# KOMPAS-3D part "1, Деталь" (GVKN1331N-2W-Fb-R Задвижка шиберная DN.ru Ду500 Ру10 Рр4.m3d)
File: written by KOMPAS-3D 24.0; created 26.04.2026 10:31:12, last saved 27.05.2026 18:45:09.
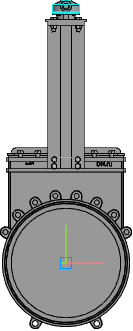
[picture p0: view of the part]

Document properties: Автор: R2D2; Полное имя файла: E:\Работа\Зайцев\АУТСОРС\Даня\GVKN1331N-2W-Fb-R Задвижка шиберная DN.ru Ду400-600 Ру4-6\исходные материалы\DN500\GVKN1331N-2W-Fb-R Задвижка шиберная DN.ru Ду500 Ру10 Рр4.m3d

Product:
- Component [standard]: Hexagon head screw ISO 4017 - М10 x 25  | qty 4  | Масса: 0.026096; Рассекать на разрезах: no; source file: C:\Program Files\ASCON\KOMPAS-3D v24\Libs\PolynomLib\DATA\vault\methods\kompas\3d\PLib_Bolt_1_ISO_1100.m3d
- Body: Тело 4  | qty 1
    Масса: 180.082087
- Body: Тело 5  | qty 1
    Масса: 180.082087
- Body: Тело 6  | qty 1
    Масса: 14.189836
- Body: Тело 7  | qty 1
    Масса: 180.082087
- Body: Тело 8  | qty 1
    Масса: 5.600139
- Body: Тело 12  | qty 1
    Масса: 5.600139
- Component [standard]: (unnamed)  | qty 4  | Масса: 0.1215; Рассекать на разрезах: no; additional columns: М16-6gx55; Болт; ГОСТ 7805-70
- Component [standard]: Гайка М16-6H ГОСТ 5915-70  | qty 4  | Масса: 0.03761; Рассекать на разрезах: no; source file: C:\Program Files\ASCON\KOMPAS-3D v24\Libs\PolynomLib\DATA\vault\methods\kompas\3d\PLib_Nut_OST92_900.m3d
- Component [standard]: Болт М18-6gx30 ГОСТ 7805-70  | qty 1  | Масса: 0.1143; Рассекать на разрезах: no; source file: C:\Program Files\ASCON\KOMPAS-3D v24\Libs\PolynomLib\DATA\vault\methods\kompas\3d\PLib_Bolt_1_900.m3d
- Component [standard]: Болт М18-6gx30 ГОСТ 7805-70  | qty 7  | Масса: 0.1143; Рассекать на разрезах: no
- Component [standard]: Болт М16-6gx30 ГОСТ 7805-70  | qty 1  | Масса: 0.08324; Рассекать на разрезах: no; source file: C:\Program Files\ASCON\KOMPAS-3D v24\Libs\PolynomLib\DATA\vault\methods\kompas\3d\PLib_Bolt_1_900.m3d
- Component [standard]: Болт М16-6gx30 ГОСТ 7805-70  | qty 7  | Масса: 0.08324; Рассекать на разрезах: no
- Body: Тело 14  | qty 1
    Масса: 180.082087
- Part/product: 1  | designation Деталь
    Масса: 18.2
    Раздел спецификации: Прочие изделия
    Примечание: D050-23732

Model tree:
1. Смещенная плоскость:2
2. Корпус
3. Элемент вращения:1
     Угол 1 = 360
4. Ушко  (with: Ребро.Элемент вращения:1)
5. Элемент выдавливания:5
6. Диск  (with: Ребро.Элемент вращения:1)
7. Элемент выдавливания:3
     Расстояние 1 = 10
8. Скругление:10  (with: Ребро.Элемент выдавливания:5)
     Радиус = 5
9. Скругление:11  (with: Ребро.Элемент выдавливания:5)
     Радиус = 2
10. Массив по концентрической сетке:7  (with: Элемент выдавливания:5, Скругление:10, Скругление:11, Грань.Элемент вращения:1)  (10 pattern instances)
11. Корпус штока
12. Элемент выдавливания:6  (with: Грань.Элемент вращения:1)
13. Эскиз:3  (with: Грань.Элемент выдавливания:5, Ребро.Скругление:11)
14. Элемент выдавливания:12
15. Массив по концентрической сетке:9  (with: Элемент выдавливания:12, Эскиз:3, Грань.Элемент вращения:1)  (17 pattern instances)
     Шаг 2 = 360
16. Зеркальный массив:2
17. Экземпляр ( 1 )
18. Экземпляр ( 2 )  (with: Массив по концентрической сетке:9, Экземпляр ( 1 ), Элемент выдавливания:12)
19. Экземпляр ( 3 )  (with: Элемент выдавливания:12)
20. Экземпляр ( 4 )  (with: Элемент выдавливания:12)
21. Экземпляр ( 5 )  (with: Элемент выдавливания:12)
22. Экземпляр ( 6 )  (with: Элемент выдавливания:12)
23. Экземпляр ( 7 )  (with: Элемент выдавливания:12)
24. Экземпляр ( 8 )  (with: Элемент выдавливания:12)
25. Экземпляр ( 9 )  (with: Элемент выдавливания:12)
26. Экземпляр ( 10 )  (with: Элемент выдавливания:12)
27. Экземпляр ( 12 )  (with: Элемент выдавливания:12)
28. Экземпляр ( 13 )  (with: Элемент выдавливания:12)
29. Экземпляр ( 14 )  (with: Элемент выдавливания:12)
30. Экземпляр ( 15 )  (with: Элемент выдавливания:12)
31. Экземпляр ( 18 )  (with: Элемент выдавливания:12)
32. Экземпляр ( 19 )  (with: Элемент выдавливания:12)
33. Экземпляр ( 20 )  (with: Элемент выдавливания:12)
34. Эскиз:24  (with: Грань.Элемент вращения:1, Ребро.Элемент вращения:1)
35. Элемент выдавливания:36
     Расстояние 2 = 2
36. Зеркальный массив:4  (with: Экземпляр ( 1 ), Экземпляр ( 2 ), Элемент выдавливания:36)
37. Резиновое уплотнение
38. Элемент выдавливания:4
39. Скругление:2  (with: Грань.Элемент выдавливания:4)
     Радиус = 2
40. Скругление:4  (with: Ребро.Элемент выдавливания:6)
     Радиус = 2
41. фланец  (with: Грань.Элемент выдавливания:6, Ребро.Элемент выдавливания:6)
42. Элемент выдавливания:13
     Расстояние 2 = 15
43. Скругление:12  (with: Ребро.Элемент выдавливания:13)
     Радиус = 10
44. Массив по сетке:1  (with: Элемент выдавливания:13, Эскиз:4, Скругление:12)  (2 pattern instances)
     Шаг 1 = 50; Угол раствора = 90
45. Эскиз:5  (with: Грань.Элемент выдавливания:6, Ребро.Элемент выдавливания:13)  (labels: Ребро.Элемент выдавливания:13.Экземпляр ( 2, 1 ))
46. Элемент выдавливания:14  (with: Грань.Элемент вращения:1)
     Расстояние 1 = 24.75; Смещение 1 = 1
47. Эскиз:6  (with: Грань.Элемент выдавливания:6, Ребро.Элемент выдавливания:13, Ребро.Элемент выдавливания:14)  (labels: Ребро.Элемент выдавливания:13.Экземпляр ( 2, 1 ))
48. Элемент выдавливания:15  (with: Грань.Элемент вращения:1)
     Расстояние 1 = 24.75; Смещение 1 = 1
49. Эскиз:7  (with: Вершина.Элемент выдавливания:14, Ребро.Элемент выдавливания:14)  (labels: Грань.Элемент выдавливания:13.Экземпляр ( 2, 1 ))
50. Элемент выдавливания:16
51. Эскиз:8  (with: Ребро.Элемент выдавливания:15)  (labels: Грань.Элемент выдавливания:13.Экземпляр ( 2, 1 ))
52. Элемент выдавливания:17  (with: Грань.Элемент выдавливания:16)
     Расстояние 1 = 670
53. Смещенная плоскость:3
54. Эскиз:9  (with: Грань.Элемент выдавливания:16, Вершина.Элемент выдавливания:17, Ребро.Элемент выдавливания:16, Ребро.Элемент выдавливания:17)
55. Элемент выдавливания:18
     Расстояние 2 = 15
56. Скругление:13  (with: Ребро.Элемент выдавливания:16, Ребро.Элемент выдавливания:17)
     Радиус = 15
57. Эскиз:10  (with: Грань.Элемент выдавливания:18, Ребро.Скругление:13, Ребро.Элемент выдавливания:18, Ребро.Элемент выдавливания:17)
58. Элемент выдавливания:19
     Расстояние 1 = 10
59. Эскиз:11  (with: Грань.Элемент выдавливания:13, Ребро.Элемент выдавливания:13)
60. Элемент выдавливания:20
     Расстояние 1 = 10
61. Эскиз:12  (with: Грань.Элемент выдавливания:20, Ребро.Элемент выдавливания:13, Ребро.Элемент выдавливания:17, Вершина.Элемент выдавливания:17, Вершина.Элемент выдавливания:18)
62. Элемент выдавливания:21
     Расстояние 1 = 10
63. Фаска:1  (with: Ребро.Элемент выдавливания:21)
     Угол = 60; Длина 1 = 20; Длина 2 = 34.641
64. Фаска:2  (with: Ребро.Элемент выдавливания:21)
     Угол = 60; Длина 1 = 20; Длина 2 = 34.641
65. Эскиз:13  (with: Грань.Элемент выдавливания:13)
66. Элемент выдавливания:22  (with: Грань.Элемент выдавливания:21)
     Расстояние 1 = 45; Смещение 1 = 25
67. Скругление:14  (with: Ребро.Элемент выдавливания:22)
     Радиус = 20
68. Эскиз:14  (with: Грань.Элемент выдавливания:21, Ребро.Элемент выдавливания:22, Ребро.Элемент выдавливания:21)
69. Элемент выдавливания:23
     Расстояние 1 = 30
70. Эскиз:15  (with: Грань.Элемент выдавливания:23, Ребро.Элемент выдавливания:23)
71. Элемент выдавливания:24  (with: Грань.Элемент выдавливания:19)
     Расстояние 1 = 570
72. Эскиз:16  (with: Грань.Элемент выдавливания:19, Ребро.Элемент выдавливания:24)
73. Элемент выдавливания:25  (with: Грань.Элемент выдавливания:18)
     Расстояние 2 = 25
74. Массив по концентрической сетке:10  (with: Элемент выдавливания:25, Эскиз:16, Грань.Элемент выдавливания:24)  (4 pattern instances)
     Шаг 2 = 360
75. Эскиз:17  (with: Грань.Элемент выдавливания:19, Ребро.Элемент выдавливания:24, Ребро.Элемент выдавливания:19)
76. Элемент выдавливания:26
     Расстояние 1 = 25
77. ИСО фланец  (with: Грань.Элемент выдавливания:26, Ребро.Элемент выдавливания:26)
78. Элемент выдавливания:7
     Расстояние 1 = 10
79. отв. исо фланца  (with: Грань.Элемент выдавливания:7, Ребро.Элемент выдавливания:7)
80. Элемент выдавливания:27  (with: Грань.Элемент выдавливания:7)
     Расстояние 2 = 10
81. Массив по концентрической сетке:11  (with: Элемент выдавливания:27, Грань.Элемент выдавливания:7)  (4 pattern instances)
     Шаг 2 = 360
82. Эскиз:18  (with: Грань.Элемент выдавливания:7, Ребро.Элемент выдавливания:7)
83. Элемент выдавливания:28
     Расстояние 1 = 2
84. Смещенная плоскость:4  (with: Грань.Элемент выдавливания:7)
     Расстояние = 0.5
85. Эскиз:19  (with: Ребро.Элемент выдавливания:7)
86. Элемент выдавливания:29
     Расстояние 1 = 30
87. Эскиз:20  (with: Ребро.Элемент выдавливания:29)
88. Элемент выдавливания:30
     Расстояние 2 = 5
89. Элемент по сечениям:1  (with: Грань.Элемент выдавливания:30, Грань.Элемент выдавливания:29)
90. Скругление:15  (with: Ребро.Элемент выдавливания:30)
     Радиус = 5
91. ЛЕЙБЛ  (with: Ребро.Скругление:4)
92. Элемент выдавливания:31  (with: Грань.Элемент выдавливания:6)
     Расстояние 1 = 29.75; Смещение 1 = 1
93. Нормальная плоскость:1  (with: Грань.Элемент выдавливания:29)
94. Эскиз:21
95. Элемент выдавливания:32
     Расстояние 1 = 100
96. Фаска:3  (with: Ребро.Элемент выдавливания:32)
     Угол = 45; Длина 1 = 10; Длина 2 = 10
97. Эскиз:22  (with: Грань.Элемент выдавливания:32, Ребро.Фаска:3)
98. Элемент выдавливания:33
     Расстояние 1 = 20
99. Массив по концентрической сетке:2  (with: Грань.Элемент выдавливания:7)  (4 pattern instances)
     Шаг 2 = 360
100. Массив по концентрической сетке:3  (with: Грань.Элемент выдавливания:26)  (4 pattern instances)
     Шаг 2 = 360
101. Эскиз:23  (with: Грань.Элемент выдавливания:16, Ребро.Элемент выдавливания:16)
102. Элемент выдавливания:34
103. Зеркальный массив:3  (with: Экземпляр ( 1 ), Экземпляр ( 2 ), Элемент выдавливания:34)
104. Эскиз:25  (labels: Грань.Элемент выдавливания:5.Экземпляр ( 1, 13 ); Ребро.Элемент выдавливания:12.Экземпляр ( 1, 13 ))
105. Элемент выдавливания:37
106. Массив по концентрической сетке:12  (with: Элемент выдавливания:37, Эскиз:25, Грань.Элемент выдавливания:7, Грань.Элемент выдавливания:19, Грань.Элемент выдавливания:18, Грань.Элемент выдавливания:21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)  (labels: Ребро.Элемент выдавливания:27.Экземпляр ( 1, 4 ); Грань.Элемент выдавливания:25.Экземпляр ( 1, 2 ); Грань.Элемент выдавливания:34.Экземпляр ( 2 ))  (12 pattern instances)
     Шаг 2 = 360

Expressions: v30-20; v161-20; D2-5; D/2-D1/2; L/2+5; 360/n/2; D1*0.85; id3-id4*2; DS*2; D1/4+10; D2-20; v4384_v161-20; H1-H1/2.5-50; H1/2.5
Referenced files in C:\Program Files\ASCON\KOMPAS-3D v24\Libs\PolynomLib\DATA\vault\Methods\Kompas\3D\: PLib_Bolt_1_ISO_1100.m3d, PLib_Bolt_1_900.m3d, PLib_Nut_OST92_900.m3d
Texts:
  BOSimple***PART:f114febc-ab7b-6638-bb5e-15f0e2e47160***SHORTLOC:A259_7B16EF33AB1642D2[16;1,5;25;10;-;Undefined]
  BOSimple***PART:d5043757-7383-cfe0-2773-bdcfb0c19ea2***SHORTLOC:Root±30±20±10±80±10±©{}30±©{BASE}130±30[Нет;Без покрытия;Без указания материала;55;16;24;2;-]
  BOSimple***PART:17b45fe1-43c8-f41a-5df4-ae57481e6c3b***SHORTLOC:Root±30±10±20±©{}110±10±50±60[Нет;Без покрытия;Без указания материала;-;16;2;24]
  BOSimple***PART:58fea51c-4c27-65e8-868c-b0420730e5b8***SHORTLOC:Root±30±20±10±80±10±©{}30±©{BASE}130±30[Нет;Без покрытия;Без указания материала;30;18;27;2,5;-]
  BOSimple***PART:296a4829-a4b6-4e05-4821-ac6adc08aeaf***SHORTLOC:Root±30±20±10±80±10±©{}30±©{BASE}130±30[Нет;Без покрытия;Без указания материала;30;16;24;2;-]
  GOST 26.020 Pr3
  var3D
  ширина затвора по металлу
  Диаметр исо фланца
  id4
  Диуметр отверстия  исо фланца
  id3
  ось отв. исо фланца
  id5
  ds1
  Hexagon head screw ISO 4017 - М10 x 25 (1)
  hole1
  hole2
  Деталь (1)
  Гайка М16-6H ГОСТ 5915-70 (1)
  bcut1
  hcut1
  cut1
  Болт М18-6gx30 ГОСТ 7805-70 (1)
  Болт М18-6gx30 ГОСТ 7805-70 (2)
  Болт М18-6gx30 ГОСТ 7805-70 (3)
  Болт М18-6gx30 ГОСТ 7805-70 (4)
  Болт М18-6gx30 ГОСТ 7805-70 (5)
  Болт М18-6gx30 ГОСТ 7805-70 (6)
  Болт М18-6gx30 ГОСТ 7805-70 (7)
  Болт М18-6gx30 ГОСТ 7805-70 (8)
  Болт М16-6gx30 ГОСТ 7805-70 (1)
  Болт М16-6gx30 ГОСТ 7805-70 (2)
  Болт М16-6gx30 ГОСТ 7805-70 (3)
  Болт М16-6gx30 ГОСТ 7805-70 (4)
  Болт М16-6gx30 ГОСТ 7805-70 (5)
  Болт М16-6gx30 ГОСТ 7805-70 (6)
  Болт М16-6gx30 ГОСТ 7805-70 (7)
  Болт М16-6gx30 ГОСТ 7805-70 (8)
  Plane. Начало координат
